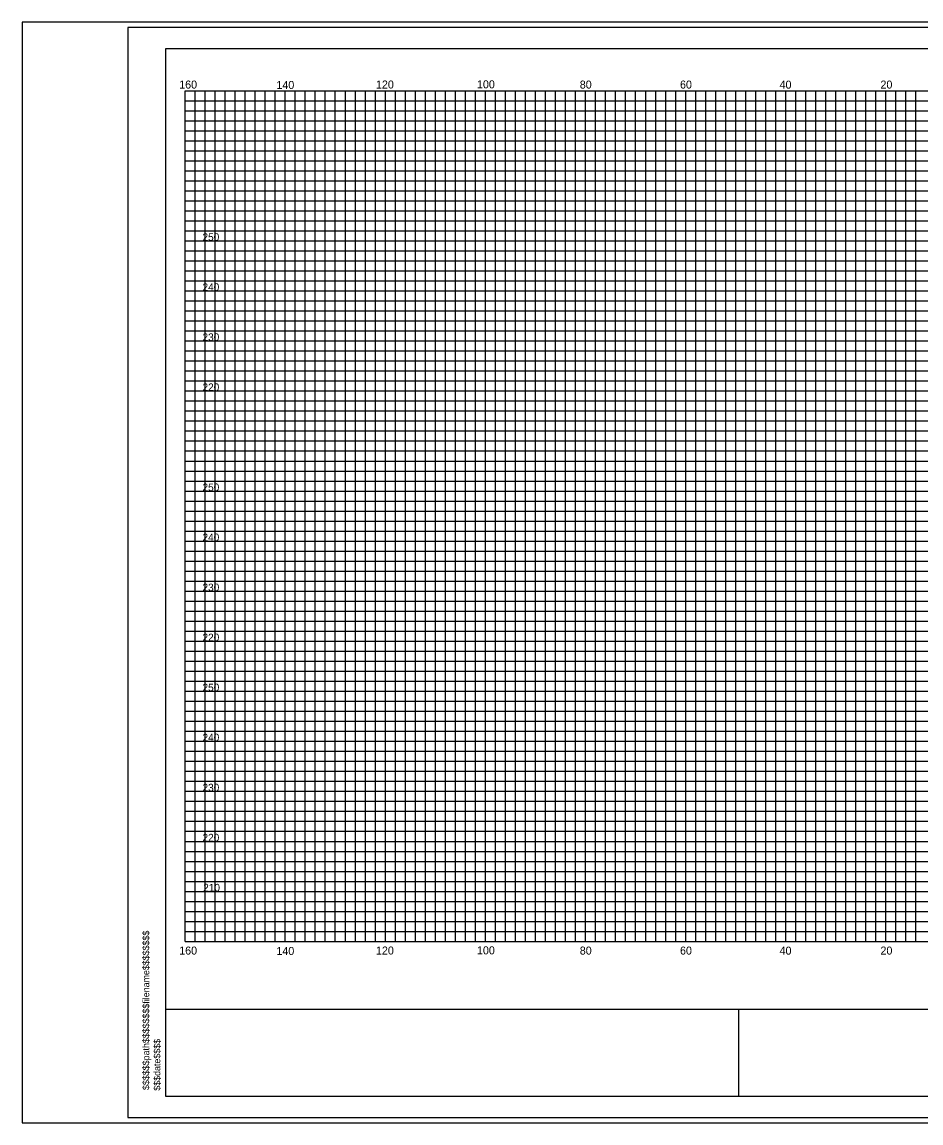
# Model space of a CAD drawing. Extents: x 967 to 1326, y 964 to 2304.
# Drawn here: x 967.4 to 1147, y 1803.7 to 2023.7 of the extents above; entities that cross this region are included whole.
import ezdxf

# ---------------------------------------------------------------- set-up
doc = ezdxf.new("R2010")
doc.units = 0
for name, color, linetype in [('Default', 7, 'Continuous'), ('RD_GPK_XS_Cell', 7, 'Continuous'), ('RD_PD_PaveShd', 7, 'Continuous'), ('RD_XS_ExGround', 7, 'Continuous'), ('RD_XS_ExPaveRet', 7, 'Continuous'), ('RD_XS_PaveOvlay', 7, 'Continuous'), ('RD_XS_TX_Elev_EX', 7, 'Continuous')]:
    doc.layers.add(name, color=color, linetype=linetype)

msp = doc.modelspace()

# ---------------------------------------------------------------- linework, layer by layer
at = {"layer": 'RD_GPK_XS_Cell'}
for p, q in [((1000, 2010), (1320, 2010)), ((1000, 1840), (1000, 2010)), ((1010, 1840), (1010, 2010)), ((1020, 1840), (1020, 2010)), ((1030, 1840), (1030, 2010)), ((1040, 1840), (1040, 2010)), ((1050, 1840), (1050, 2010)), ((1060, 1840), (1060, 2010)), ((1070, 1840), (1070, 2010)), ((1080, 1840), (1080, 2010)), ((1090, 1840), (1090, 2010)), ((1100, 1840), (1100, 2010)), ((1110, 1840), (1110, 2010)), ((1120, 1840), (1120, 2010)), ((1130, 1840), (1130, 2010)), ((1140, 1840), (1140, 2010)), ((1000, 2000), (1320, 2000)), ((1000, 1990), (1320, 1990)), ((1000, 1980), (1320, 1980)), ((1000, 1970), (1320, 1970)), ((1000, 1960), (1320, 1960)), ((1000, 1950), (1320, 1950)), ((1000, 1940), (1320, 1940)), ((1000, 1930), (1320, 1930)), ((1000, 1920), (1320, 1920)), ((1000, 1910), (1320, 1910)), ((1000, 1900), (1320, 1900)), ((1000, 1890), (1320, 1890)), ((1000, 1880), (1320, 1880)), ((1000, 1870), (1320, 1870)), ((1000, 1860), (1320, 1860)), ((1000, 1850), (1320, 1850)), ((1000, 1840), (1320, 1840))]:
    msp.add_line(p, q, dxfattribs=at)
at = {"layer": 'RD_PD_PaveShd'}
for p, q in [((996.11, 1808.98), (996.11, 2018.46)), ((996.11, 2018.46), (1323.89, 2018.46)), ((996.11, 1826.49), (1323.89, 1826.49)), ((1110.59, 1808.98), (1110.59, 1826.56)), ((1323.89, 1808.98), (996.11, 1808.98))]:
    msp.add_line(p, q, dxfattribs=at)
at = {"layer": 'RD_XS_ExGround'}
for p, q in [((1002, 1840), (1002, 2010)), ((1004, 1840), (1004, 2010)), ((1006, 1840), (1006, 2010)), ((1008, 1840), (1008, 2010)), ((1012, 1840), (1012, 2010)), ((1014, 1840), (1014, 2010)), ((1016, 1840), (1016, 2010)), ((1018, 1840), (1018, 2010)), ((1022, 1840), (1022, 2010)), ((1024, 1840), (1024, 2010)), ((1026, 1840), (1026, 2010)), ((1028, 1840), (1028, 2010)), ((1032, 1840), (1032, 2010)), ((1034, 1840), (1034, 2010)), ((1036, 1840), (1036, 2010)), ((1038, 1840), (1038, 2010)), ((1042, 1840), (1042, 2010)), ((1044, 1840), (1044, 2010)), ((1046, 1840), (1046, 2010)), ((1048, 1840), (1048, 2010)), ((1052, 1840), (1052, 2010)), ((1054, 1840), (1054, 2010)), ((1056, 1840), (1056, 2010)), ((1058, 1840), (1058, 2010)), ((1062, 1840), (1062, 2010)), ((1064, 1840), (1064, 2010)), ((1066, 1840), (1066, 2010)), ((1068, 1840), (1068, 2010)), ((1072, 1840), (1072, 2010)), ((1074, 1840), (1074, 2010)), ((1076, 1840), (1076, 2010)), ((1078, 1840), (1078, 2010)), ((1082, 1840), (1082, 2010)), ((1084, 1840), (1084, 2010)), ((1086, 1840), (1086, 2010)), ((1088, 1840), (1088, 2010)), ((1092, 1840), (1092, 2010)), ((1094, 1840), (1094, 2010)), ((1096, 1840), (1096, 2010)), ((1098, 1840), (1098, 2010)), ((1102, 1840), (1102, 2010)), ((1104, 1840), (1104, 2010)), ((1106, 1840), (1106, 2010)), ((1108, 1840), (1108, 2010)), ((1112, 1840), (1112, 2010)), ((1114, 1840), (1114, 2010)), ((1116, 1840), (1116, 2010)), ((1118, 1840), (1118, 2010)), ((1122, 1840), (1122, 2010)), ((1124, 1840), (1124, 2010)), ((1126, 1840), (1126, 2010)), ((1128, 1840), (1128, 2010)), ((1132, 1840), (1132, 2010)), ((1134, 1840), (1134, 2010)), ((1136, 1840), (1136, 2010)), ((1138, 1840), (1138, 2010)), ((1142, 1840), (1142, 2010)), ((1144, 1840), (1144, 2010)), ((1146, 1840), (1146, 2010)), ((1000, 2008), (1320, 2008)), ((1000, 2006), (1320, 2006)), ((1000, 2004), (1320, 2004)), ((1000, 2002), (1320, 2002)), ((1000, 1998), (1320, 1998)), ((1000, 1996), (1320, 1996)), ((1000, 1994), (1320, 1994)), ((1000, 1992), (1320, 1992)), ((1000, 1988), (1320, 1988)), ((1000, 1986), (1320, 1986)), ((1000, 1984), (1320, 1984)), ((1000, 1982), (1320, 1982)), ((1000, 1978), (1320, 1978)), ((1000, 1976), (1320, 1976)), ((1000, 1974), (1320, 1974)), ((1000, 1972), (1320, 1972)), ((1000, 1968), (1320, 1968)), ((1000, 1966), (1320, 1966)), ((1000, 1964), (1320, 1964)), ((1000, 1962), (1320, 1962)), ((1000, 1958), (1320, 1958)), ((1000, 1956), (1320, 1956)), ((1000, 1954), (1320, 1954)), ((1000, 1952), (1320, 1952)), ((1000, 1948), (1320, 1948)), ((1000, 1946), (1320, 1946)), ((1000, 1944), (1320, 1944)), ((1000, 1942), (1320, 1942)), ((1000, 1938), (1320, 1938)), ((1000, 1936), (1320, 1936)), ((1000, 1934), (1320, 1934)), ((1000, 1932), (1320, 1932)), ((1000, 1928), (1320, 1928)), ((1000, 1926), (1320, 1926)), ((1000, 1924), (1320, 1924)), ((1000, 1922), (1320, 1922)), ((1000, 1918), (1320, 1918)), ((1000, 1916), (1320, 1916)), ((1000, 1914), (1320, 1914)), ((1000, 1912), (1320, 1912)), ((1000, 1908), (1320, 1908)), ((1000, 1906), (1320, 1906)), ((1000, 1904), (1320, 1904)), ((1000, 1902), (1320, 1902)), ((1000, 1898), (1320, 1898)), ((1000, 1896), (1320, 1896)), ((1000, 1894), (1320, 1894)), ((1000, 1892), (1320, 1892)), ((1000, 1888), (1320, 1888)), ((1000, 1886), (1320, 1886)), ((1000, 1884), (1320, 1884)), ((1000, 1882), (1320, 1882)), ((1000, 1878), (1320, 1878)), ((1000, 1876), (1320, 1876)), ((1000, 1874), (1320, 1874)), ((1000, 1872), (1320, 1872)), ((1000, 1868), (1320, 1868)), ((1000, 1866), (1320, 1866)), ((1000, 1864), (1320, 1864)), ((1000, 1862), (1320, 1862)), ((1000, 1858), (1320, 1858)), ((1000, 1856), (1320, 1856)), ((1000, 1854), (1320, 1854)), ((1000, 1852), (1320, 1852)), ((1000, 1848), (1320, 1848)), ((1000, 1846), (1320, 1846)), ((1000, 1844), (1320, 1844)), ((1000, 1842), (1320, 1842))]:
    msp.add_line(p, q, dxfattribs=at)
at = {"layer": 'RD_XS_PaveOvlay'}
msp.add_lwpolyline([(967.41, 1803.72), (1326.28, 1803.72), (1326.28, 2023.72), (967.41, 2023.72)], close=True, dxfattribs=at)
at = {"layer": 'RD_XS_TX_Elev_EX'}
for points in [[(967.41, 1803.72), (1326.28, 1803.72), (1326.28, 2023.72), (967.41, 2023.72)], [(988.52, 1804.84), (1326.28, 1804.84), (1326.28, 2022.6), (988.52, 2022.6)]]:
    msp.add_lwpolyline(points, close=True, dxfattribs=at)

# ---------------------------------------------------------------- texts
at = {"layer": 'Default'}
for s, p in [('250', (1003.47, 1980)), ('240', (1003.47, 1970)), ('230', (1003.47, 1960)), ('220', (1003.47, 1950)), ('250', (1003.47, 1930)), ('240', (1003.47, 1920)), ('230', (1003.47, 1910)), ('220', (1003.47, 1900)), ('250', (1003.47, 1890)), ('240', (1003.47, 1880)), ('230', (1003.47, 1870)), ('220', (1003.47, 1860)), ('210', (1003.61, 1850))]:
    msp.add_text(s, height=1.5, dxfattribs=at).set_placement(p)
for s, p in [('$$$$$$path$$$$$$$$filename$$$$$$$$', (992.83, 1810.31)), ('$$$date$$$$', (995.04, 1810.17))]:
    msp.add_text(s, height=1.3258, rotation=90, dxfattribs=at).set_placement(p)
at = {"layer": 'RD_XS_ExPaveRet'}
for s, p in [('160', (998.81, 2010.42)), ('140', (1018.23, 2010.34)), ('120', (1038.12, 2010.43)), ('100', (1058.3, 2010.47)), ('80', (1078.84, 2010.42)), ('60', (1098.86, 2010.42)), ('40', (1118.75, 2010.41)), ('20', (1138.91, 2010.42)), ('160', (998.81, 1837.37)), ('140', (1018.23, 1837.29)), ('120', (1038.12, 1837.38)), ('100', (1058.3, 1837.42)), ('80', (1078.84, 1837.37)), ('60', (1098.86, 1837.37)), ('40', (1118.75, 1837.36)), ('20', (1138.91, 1837.37))]:
    msp.add_text(s, height=1.6, dxfattribs=at).set_placement(p)

doc.saveas('drawing.dxf')
